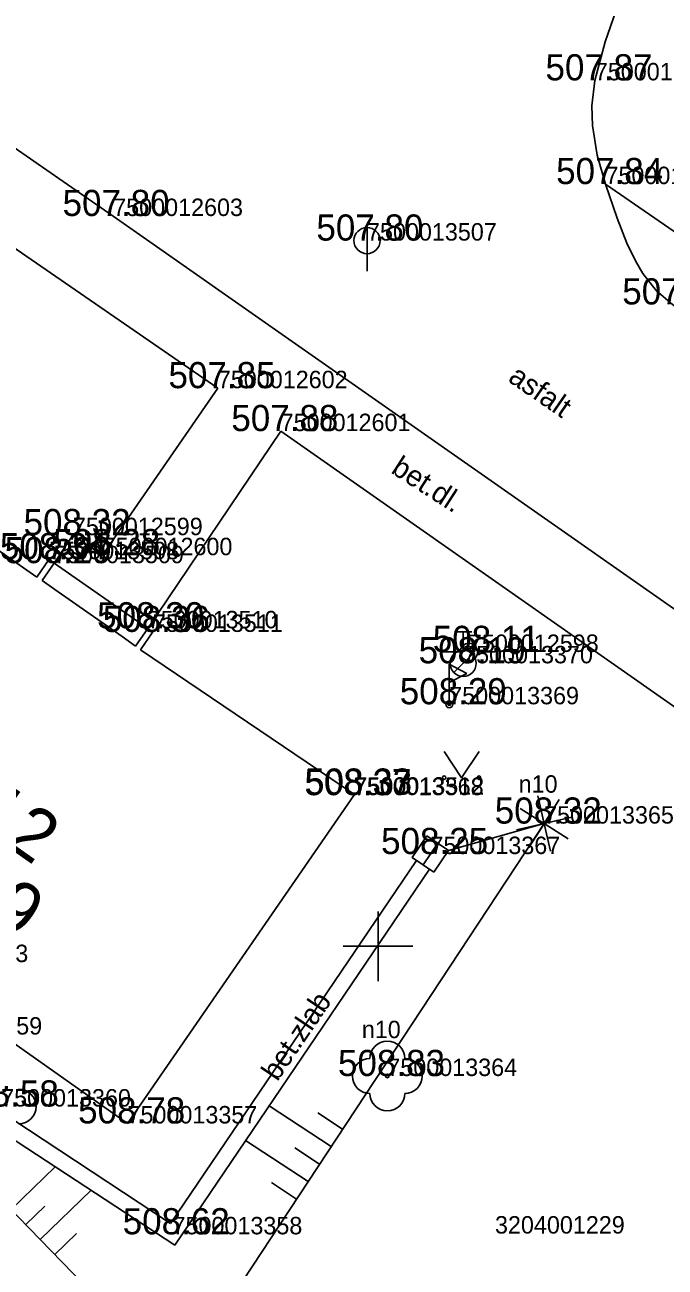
# Model space of a CAD drawing. Extents: x -669251 to -668549, y -1128351 to -1127698.
# Drawn here: x -668910.12 to -668891.77, y -1127809.2 to -1127773.58 of the extents above; entities that cross this region are included whole.
import ezdxf

# ---------------------------------------------------------------- set-up
doc = ezdxf.new("R2010")
doc.units = 0
for name, color, linetype in [('Vrstva 1', 7, 'Continuous'), ('Vrstva 10', 7, 'Continuous'), ('Vrstva 14', 7, 'Continuous'), ('Vrstva 15', 7, 'Continuous'), ('Vrstva 2', 7, 'Continuous'), ('Vrstva 22', 7, 'Continuous'), ('Vrstva 27', 7, 'Continuous'), ('Vrstva 28', 7, 'Continuous'), ('Vrstva 3', 7, 'Continuous'), ('Vrstva 36', 7, 'Continuous'), ('Vrstva 40', 7, 'Continuous'), ('Vrstva 43', 7, 'Continuous'), ('Vrstva 44', 7, 'Continuous'), ('Vrstva 47', 7, 'Continuous'), ('Vrstva 5', 7, 'Continuous'), ('Vrstva 6', 7, 'Continuous'), ('Vrstva 61', 7, 'Continuous')]:
    doc.layers.add(name, color=color, linetype=linetype)

msp = doc.modelspace()

# ---------------------------------------------------------------- linework, layer by layer
at = {"layer": 'Vrstva 1'}
for p, q in [((-668893.788, -1127775.168), (-668893.788, -1127775.168)), ((-668893.483, -1127778.143), (-668893.483, -1127778.143)), ((-668907.589, -1127779.058), (-668907.589, -1127779.058)), ((-668900.317, -1127779.763), (-668900.317, -1127779.763)), ((-668904.591, -1127783.996), (-668904.591, -1127783.996)), ((-668902.79, -1127785.227), (-668902.79, -1127785.227)), ((-668908.743, -1127788.211), (-668908.743, -1127788.211)), ((-668909.42, -1127788.902), (-668909.42, -1127788.902)), ((-668909.283, -1127789.014), (-668909.283, -1127789.014)), ((-668907.892, -1127788.785), (-668907.892, -1127788.785)), ((-668906.6, -1127790.883), (-668906.6, -1127790.883)), ((-668906.451, -1127790.986), (-668906.451, -1127790.986)), ((-668897.396, -1127791.56), (-668897.396, -1127791.56)), ((-668897.562, -1127791.886), (-668897.562, -1127791.886)), ((-668897.961, -1127793.061), (-668897.961, -1127793.061)), ((-668900.695, -1127795.668), (-668900.695, -1127795.668)), ((-668900.677, -1127795.652), (-668900.677, -1127795.652)), ((-668895.242, -1127796.483), (-668895.242, -1127796.483)), ((-668898.499, -1127797.356), (-668898.499, -1127797.356)), ((-668899.734, -1127803.722), (-668899.734, -1127803.722)), ((-668907.18, -1127805.082), (-668907.18, -1127805.082)), ((-668905.889, -1127808.262), (-668905.889, -1127808.262)), ((-668896.65, -1127808.24), (-668896.65, -1127808.24))]:
    msp.add_line(p, q, dxfattribs=at)
at = {"layer": 'Vrstva 10'}
for p, q in [((-668947.059, -1127751.764), (-668907.589, -1127779.058)), ((-668904.591, -1127783.996), (-668917.603, -1127775.031)), ((-668893.483, -1127778.143), (-668873.834, -1127791.773)), ((-668907.589, -1127779.058), (-668856.591, -1127814.83)), ((-668907.892, -1127788.785), (-668904.591, -1127783.996)), ((-668902.79, -1127785.227), (-668906.6, -1127790.883)), ((-668902.79, -1127785.227), (-668884.997, -1127797.698)), ((-668909.283, -1127789.014), (-668908.743, -1127788.211)), ((-668908.743, -1127788.211), (-668907.892, -1127788.785)), ((-668898.896, -1127797.541), (-668905.952, -1127807.954)), ((-668898.523, -1127797.793), (-668905.826, -1127808.57)), ((-668905.952, -1127807.954), (-668914.367, -1127802.413)), ((-668905.826, -1127808.57), (-668914.621, -1127802.807))]:
    msp.add_line(p, q, dxfattribs=at)
msp.add_lwpolyline([(-668887.358, -1127764.319), (-668889.806, -1127767.851), (-668892.255, -1127771.383), (-668892.781, -1127772.263), (-668893.106, -1127772.966), (-668893.497, -1127774.06), (-668893.788, -1127775.168), (-668893.877, -1127775.9), (-668893.859, -1127776.462), (-668893.721, -1127777.31), (-668893.483, -1127778.143), (-668893.153, -1127779.116), (-668892.872, -1127779.835), (-668892.624, -1127780.346), (-668892.409, -1127780.705), (-668892.029, -1127781.19), (-668891.565, -1127781.595), (-668865.775, -1127799.672), (-668839.985, -1127817.748)], dxfattribs=at)
at = {"layer": 'Vrstva 14'}
for p, q in [((-668905.762, -1127812.449), (-668895.242, -1127796.483)), ((-668895.242, -1127796.483), (-668897.979, -1127797.255)), ((-668914.82, -1127803.115), (-668905.762, -1127812.449))]:
    msp.add_line(p, q, dxfattribs=at)
at = {"layer": 'Vrstva 15'}
for p, q in [((-668901.346, -1127805.747), (-668903.121, -1127804.578)), ((-668901.016, -1127805.246), (-668901.723, -1127804.78)), ((-668902.006, -1127806.749), (-668903.794, -1127805.571)), ((-668901.676, -1127806.248), (-668902.389, -1127805.779)), ((-668910.514, -1127807.552), (-668909.251, -1127806.326)), ((-668902.336, -1127807.25), (-668903.054, -1127806.777)), ((-668909.679, -1127808.413), (-668908.222, -1127807)), ((-668910.096, -1127807.983), (-668909.552, -1127807.455)), ((-668909.26, -1127808.844), (-668908.639, -1127808.241))]:
    msp.add_line(p, q, dxfattribs=at)
at = {"layer": 'Vrstva 22'}
for p, q in [((-668895.25, -1127796.443), (-668895.422, -1127795.689)), ((-668894.808, -1127795.793), (-668895.222, -1127796.449)), ((-668895.276, -1127796.463), (-668895.932, -1127796.049)), ((-668896.036, -1127796.663), (-668895.282, -1127796.491)), ((-668895.262, -1127796.517), (-668895.676, -1127797.173)), ((-668895.234, -1127796.523), (-668895.062, -1127797.277)), ((-668894.552, -1127796.917), (-668895.208, -1127796.503)), ((-668895.202, -1127796.475), (-668894.448, -1127796.303))]:
    msp.add_line(p, q, dxfattribs=at)
for centre, radius in [((-668895.242, -1127796.483), 0.04), ((-668899.734, -1127803.722), 0.05)]:
    msp.add_circle(centre, radius, dxfattribs=at)
for centre, start, end in [((-668899.734, -1127803.222), 0, 180), ((-668900.234, -1127803.722), 90, 270), ((-668899.234, -1127803.722), 270, 90), ((-668910.3, -1127804.597), 270, 90), ((-668899.734, -1127804.222), 180, 0)]:
    msp.add_arc(centre, 0.5, start, end, dxfattribs=at)
at = {"layer": 'Vrstva 27'}
for p, q in [((-668900.317, -1127779.388), (-668900.317, -1127780.638)), ((-668898.709, -1127797.666), (-668898.289, -1127797.046))]:
    msp.add_line(p, q, dxfattribs=at)
msp.add_lwpolyline([(-668898.4, -1127797.876), (-668897.979, -1127797.255), (-668898.6, -1127796.835), (-668899.021, -1127797.456)], close=True, dxfattribs=at)
msp.add_circle((-668900.317, -1127779.763), 0.375, dxfattribs=at)
at = {"layer": 'Vrstva 28'}
for p, q in [((-668897.812, -1127790.986), (-668897.312, -1127790.986)), ((-668897.562, -1127791.511), (-668897.562, -1127790.986)), ((-668897.646, -1127791.56), (-668898.146, -1127791.56)), ((-668897.146, -1127791.56), (-668896.646, -1127791.56)), ((-668897.961, -1127793.061), (-668897.961, -1127791.911)), ((-668897.961, -1127791.911), (-668897.461, -1127792.176)), ((-668897.827, -1127792.151), (-668897.297, -1127791.621)), ((-668897.461, -1127792.176), (-668897.961, -1127792.441))]:
    msp.add_line(p, q, dxfattribs=at)
for centre, radius in [((-668897.562, -1127791.886), 0.375), ((-668897.396, -1127791.56), 0.25), ((-668897.961, -1127793.061), 0.1), ((-668897.961, -1127793.061), 0.0348)]:
    msp.add_circle(centre, radius, dxfattribs=at)
at = {"layer": 'Vrstva 36'}
for p, q in [((-668898.106, -1127794.416), (-668897.606, -1127795.166)), ((-668897.606, -1127795.166), (-668897.106, -1127794.416))]:
    msp.add_line(p, q, dxfattribs=at)
for centre in [(-668898.106, -1127795.166), (-668897.106, -1127795.166)]:
    msp.add_circle(centre, 0.05, dxfattribs=at)
at = {"layer": 'Vrstva 5'}
for p, q in [((-668921.588, -1127781.228), (-668909.773, -1127789.412)), ((-668909.773, -1127789.412), (-668909.42, -1127788.902)), ((-668909.629, -1127789.513), (-668909.283, -1127789.014)), ((-668909.42, -1127788.902), (-668909.283, -1127789.014)), ((-668906.6, -1127790.883), (-668909.283, -1127789.014)), ((-668909.629, -1127789.513), (-668909.261, -1127789.771)), ((-668906.953, -1127791.391), (-668906.6, -1127790.883)), ((-668906.6, -1127790.883), (-668906.451, -1127790.986)), ((-668906.953, -1127791.391), (-668907.337, -1127791.121)), ((-668906.804, -1127791.496), (-668906.451, -1127790.986)), ((-668906.804, -1127791.496), (-668900.677, -1127795.652)), ((-668907.18, -1127805.082), (-668900.677, -1127795.652)), ((-668913.273, -1127800.786), (-668907.18, -1127805.082))]:
    msp.add_line(p, q, dxfattribs=at)
at = {"layer": 'Vrstva 6'}
msp.add_line((-668907.337, -1127791.121), (-668909.261, -1127789.771), dxfattribs=at)
at = {"layer": 'Vrstva 61'}
for p, q in [((-668900, -1127799), (-668900, -1127801)), ((-668901, -1127800), (-668899, -1127800))]:
    msp.add_line(p, q, dxfattribs=at)

# ---------------------------------------------------------------- texts
at = {"layer": 'Vrstva 2'}
for s, p in [('7500012625', (-668893.788, -1127775.168)), ('7500012626', (-668893.483, -1127778.143)), ('7500012603', (-668907.589, -1127779.058)), ('7500013507', (-668900.317, -1127779.763)), ('7500012602', (-668904.591, -1127783.996)), ('7500012601', (-668902.79, -1127785.227)), ('7500012599', (-668908.743, -1127788.211)), ('7500013508', (-668909.42, -1127788.902)), ('7500012600', (-668907.892, -1127788.785)), ('7500013509', (-668909.283, -1127789.014)), ('7500013510', (-668906.6, -1127790.883)), ('7500013511', (-668906.451, -1127790.986)), ('7500012598', (-668897.396, -1127791.56)), ('7500013370', (-668897.562, -1127791.886)), ('7500013369', (-668897.961, -1127793.061)), ('7500013368', (-668900.695, -1127795.668)), ('7500013512', (-668900.677, -1127795.652)), ('7500013365', (-668895.242, -1127796.483)), ('7500013367', (-668898.499, -1127797.356)), ('7500013353', (-668913.742, -1127800.455)), ('7500013359', (-668913.343, -1127802.532)), ('7500013364', (-668899.734, -1127803.722)), ('7500013360', (-668910.8, -1127804.597)), ('7500013357', (-668907.18, -1127805.082)), ('7500013358', (-668905.889, -1127808.262)), ('3204001229', (-668896.65, -1127808.24))]:
    msp.add_text(s, height=0.5, dxfattribs=at).set_placement(p)
at = {"layer": 'Vrstva 3'}
for s, p in [('507.87 ', (-668895.203, -1127775.168)), ('507.84 ', (-668894.898, -1127778.143)), ('507.80 ', (-668909.04, -1127779.058)), ('507.80 ', (-668901.768, -1127779.763)), ('507.86 ', (-668893.003, -1127781.595)), ('507.85 ', (-668906.006, -1127783.996)), ('507.88 ', (-668904.205, -1127785.227)), ('508.32 ', (-668910.158, -1127788.211)), ('508.28 ', (-668909.307, -1127788.785)), ('508.34 ', (-668910.835, -1127788.902)), ('508.29 ', (-668910.701, -1127789.014)), ('508.30 ', (-668908.051, -1127790.883)), ('508.36 ', (-668907.889, -1127790.986)), ('508.11 ', (-668898.433, -1127791.56)), ('508.19 ', (-668898.838, -1127791.886)), ('508.29 ', (-668899.379, -1127793.061)), ('508.37 ', (-668902.11, -1127795.668)), ('508.33 ', (-668902.092, -1127795.652)), ('508.32 ', (-668896.657, -1127796.483)), ('508.25 ', (-668899.914, -1127797.356)), ('508.83 ', (-668901.149, -1127803.722)), ('508.58 ', (-668912.215, -1127804.597)), ('508.78 ', (-668908.595, -1127805.082)), ('508.62 ', (-668907.318, -1127808.262))]:
    msp.add_text(s, height=0.75, dxfattribs=at).set_placement(p)
at = {"layer": 'Vrstva 40'}
for s, rotation, p in [('asfalt', 325.3967, (-668896.306, -1127783.779)), ('bet.dl.', 327.238, (-668899.66, -1127786.408)), ('bet.zlab', 55.8781, (-668902.886, -1127803.899))]:
    msp.add_text(s, height=0.6, rotation=rotation, dxfattribs=at).set_placement(p)
at = {"layer": 'Vrstva 43'}
msp.add_text('4219', height=1.5, rotation=324.8116, dxfattribs=at).set_placement((-668913.931, -1127797.262))
at = {"layer": 'Vrstva 44'}
msp.add_text('12', height=1.5, rotation=324.8116, dxfattribs=at).set_placement((-668911.672, -1127796.409))
at = {"layer": 'Vrstva 47'}
for height, p in [(0.5, (-668895.972, -1127795.597)), (0.499, (-668900.464, -1127802.636))]:
    msp.add_text('n10', height=height, dxfattribs=at).set_placement(p)

doc.saveas('drawing.dxf')
